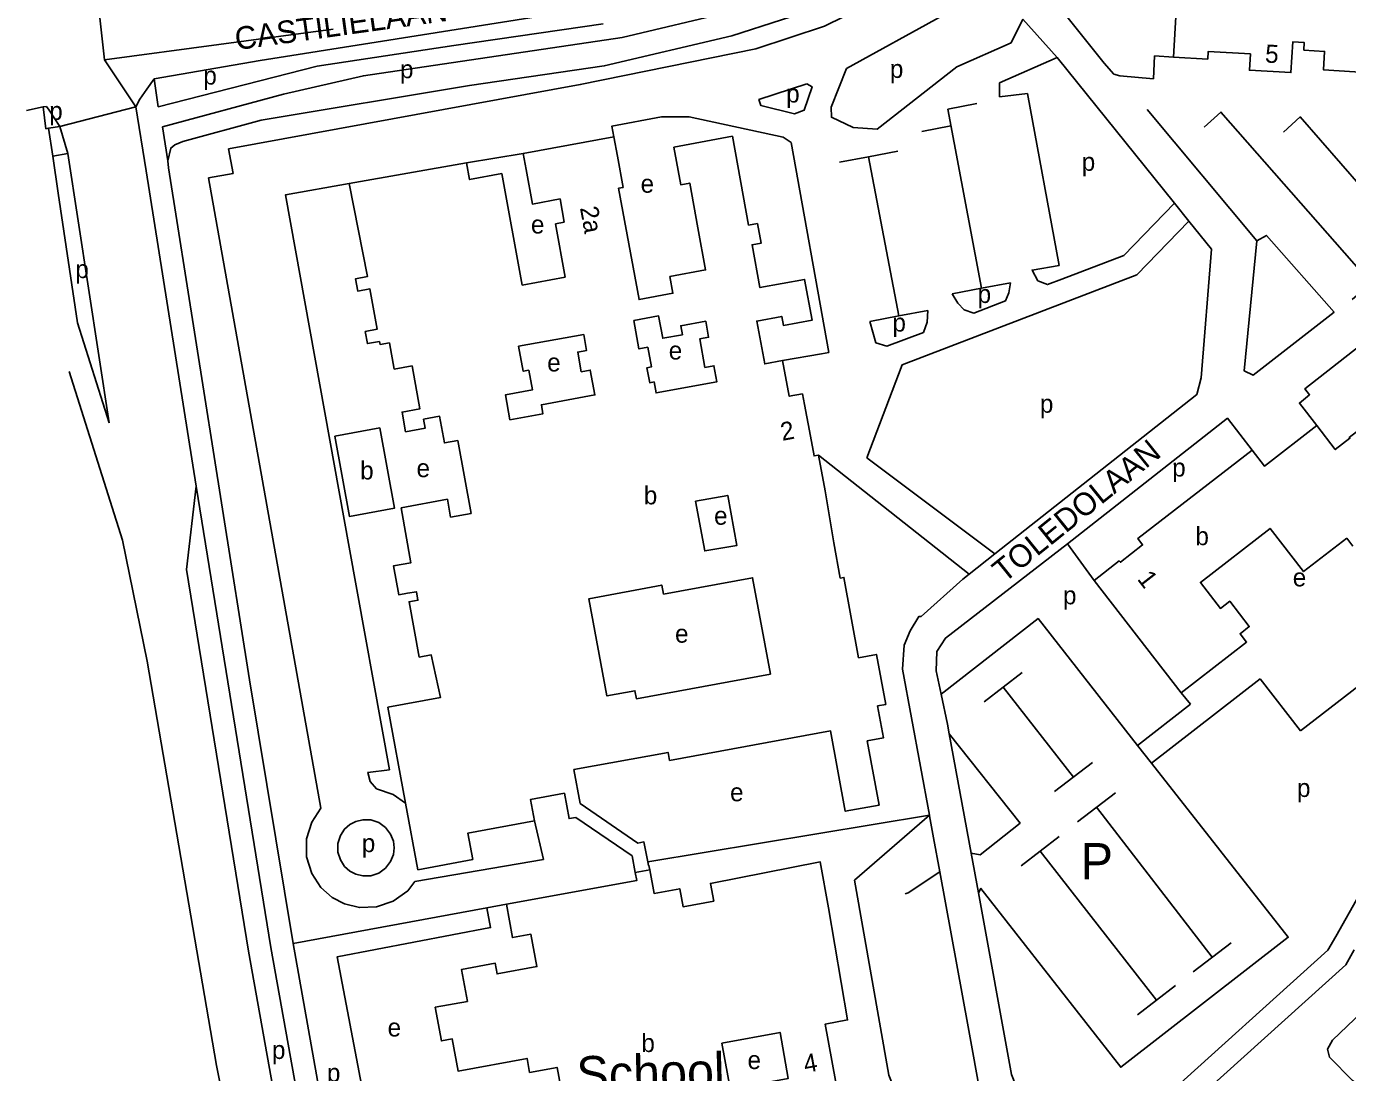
# Model space of a CAD drawing. Extents: x 159441 to 162086, y 388175 to 389787.
# Drawn here: x 159474.3 to 159765.8, y 388873.9 to 389104.6 of the extents above; entities that cross this region are included whole.
import ezdxf

# ---------------------------------------------------------------- set-up
doc = ezdxf.new("R2010")
doc.units = 0
for name, color, linetype in [('BLT_Basislijn', 7, 'Continuous'), ('BLT_Bebouwing', 7, 'Continuous'), ('BLT_Bebouwing_beschrifting', 7, 'Continuous'), ('BLT_Centroide', 7, 'Continuous'), ('BLT_Huisnummer', 7, 'Continuous'), ('BLT_Huisnummer_reeks', 7, 'Continuous'), ('BLT_Onderverdeling_panden', 7, 'Continuous'), ('BLT_Straatnaam', 7, 'Continuous'), ('BLT_Tekst_parkeren', 7, 'Continuous'), ('BLT_Vlakafsluiter', 7, 'Continuous')]:
    doc.layers.add(name, color=color, linetype=linetype)

msp = doc.modelspace()

# ---------------------------------------------------------------- linework, layer by layer
at = {"layer": 'BLT_Basislijn'}
for p, q in [((159568.59, 389100.37), (159601.53, 389105.17)), ((159541.95, 389104.04), (159491.51, 389097.27)), ((159538.39, 389095.84), (159568.59, 389100.37)), ((159727.33, 389097.85), (159723.18, 389098.14)), ((159479.24, 389086.16), (159478.7, 389086.98)), ((159677.54, 389086.37), (159683.95, 389087.58)), ((159498.37, 389086.88), (159500.66, 389072.78)), ((159677.54, 389086.37), (159684.95, 389046.87)), ((159479.15, 389082.14), (159481.62, 389082.54)), ((159671.82, 389081.47), (159678.23, 389082.68)), ((159480.07, 389075.99), (159483.43, 389076.56)), ((159583.85, 389076.61), (159571.34, 389074.53)), ((159653.67, 389074.66), (159660.08, 389075.87)), ((159660.08, 389075.87), (159666.49, 389077.08)), ((159511.68, 389003.22), (159500.66, 389072.78)), ((159678.54, 389045.66), (159684.95, 389046.87)), ((159684.95, 389046.87), (159691.36, 389048.08)), ((159660.31, 389039.55), (159666.71, 389040.76)), ((159666.71, 389040.76), (159673.12, 389041.97)), ((159682.24, 388983.81), (159649, 389010.05)), ((159509.6, 388984.81), (159511.68, 389003.22)), ((159682.24, 388983.81), (159687.91, 388988.28)), ((159709.85, 388982.41), (159703.94, 388990.47)), ((159685.55, 388955.64), (159693.92, 388962.08)), ((159689.73, 388958.86), (159705.3, 388939.04)), ((159722.51, 388942.1), (159746.45, 388960.72)), ((159719.42, 388946.03), (159731.07, 388955.09)), ((159719.42, 388946.03), (159722.51, 388942.1)), ((159701.11, 388935.82), (159709.49, 388942.26)), ((159706.15, 388929.16), (159714.53, 388935.59)), ((159611.35, 388920.37), (159673.49, 388930.61)), ((159710.34, 388932.38), (159735.88, 388899.29)), ((159674.38, 388925.61), (159675.81, 388918.17)), ((159693.72, 388919.47), (159702.1, 388925.91)), ((159697.91, 388922.69), (159723.58, 388889.81)), ((159533.12, 388902.32), (159575.83, 388910.17)), ((159575.83, 388910.17), (159580.15, 388911)), ((159731.69, 388896.07), (159740.07, 388902.51)), ((159719.39, 388886.59), (159727.77, 388893.03))]:
    msp.add_line(p, q, dxfattribs=at)
for points in [[(159525.86, 389097.11), (159551.4, 389101.15), (159604.37, 389109.5), (159624.03, 389113.78), (159632.93, 389116.43), (159648.23, 389121.53), (159666.92, 389129.4), (159672.01, 389132.06)], [(159504.28, 389082.44), (159530.95, 389089.7), (159548.62, 389093.73), (159605.67, 389102.2), (159629.93, 389107.91), (159644.32, 389112.21), (159664.93, 389120.53), (159679.73, 389127.81)], [(159688.15, 389129.13), (159695.07, 389117.86), (159712.06, 389096.47), (159714.2, 389094.06), (159715.53, 389093.71), (159722.91, 389093.05)], [(159505.46, 389074.96), (159506.1, 389077.76), (159506.99, 389078.46), (159508.78, 389079.21), (159526.06, 389083.91), (159572.01, 389091.55), (159601.73, 389095.89), (159629.93, 389102.55), (159651.83, 389109.56), (159662.94, 389114.27), (159681.99, 389123.7)], [(159694.13, 389106.22), (159691.51, 389100.96), (159679.57, 389095.67), (159661.96, 389081.94), (159656.66, 389082.33), (159651.86, 389084.58), (159651.82, 389086.78), (159655.2, 389095.33), (159676.31, 389106.98), (159673.6, 389111.89), (159671.73, 389115.27), (159650.36, 389104.68), (159635.16, 389099.67), (159596.44, 389091.79), (159518.87, 389077.6), (159519.87, 389072.19), (159514.45, 389071.2), (159539.21, 388932.17)], [(159694.13, 389106.22), (159701.68, 389097.78)], [(159525.86, 389097.11), (159502.44, 389093.04)], [(159502.44, 389093.04), (159503.35, 389086.91), (159538.39, 389095.84)], [(159688.96, 389089.06), (159688.96, 389092.14), (159701.68, 389097.78)], [(159727.57, 389065.59), (159701.68, 389097.78)], [(159723.18, 389098.14), (159722.91, 389093.05)], [(159502.44, 389093.04), (159500.79, 389090.79), (159499.29, 389088.55), (159498.37, 389086.88)], [(159477.92, 389086.87), (159478.7, 389086.98)], [(159688.96, 389089.06), (159695.12, 389089.8), (159702.13, 389051.9)], [(159479.15, 389082.14), (159478.56, 389082.05), (159477.92, 389086.87)], [(159479.24, 389086.16), (159480.35, 389084.48), (159481.62, 389082.54)], [(159641.1, 389030.9), (159649.66, 389032.43), (159651.28, 389032.72), (159642.98, 389078.99), (159641.21, 389080.22), (159620.48, 389084.7), (159614.39, 389084.68), (159603.4, 389082.61), (159603.87, 389080.25)], [(159721.55, 389086.27), (159745.75, 389057.32)], [(159734.1, 389082.4), (159737.82, 389085.73), (159770.97, 389047.99), (159766.8, 389044.4)], [(159751.6, 389081.32), (159755.32, 389084.64), (159777.7, 389058.95), (159773.53, 389055.36)], [(159479.15, 389082.14), (159480.07, 389075.99)], [(159481.62, 389082.54), (159481.62, 389082.54), (159483.43, 389076.56)], [(159505.46, 389074.96), (159504.28, 389082.44)], [(159480.07, 389075.99), (159481.29, 389067.86), (159485.55, 389039.22)], [(159483.43, 389076.56), (159492.52, 389017.15)], [(159660.08, 389075.87), (159666.71, 389040.76)], [(159533.12, 388902.32), (159523.51, 388960.52), (159505.62, 389073.43), (159505.46, 389074.96)], [(159551.47, 388936.47), (159550.11, 388938.04), (159549.57, 388940.05), (159554.36, 388940.66), (159545.47, 388989.77), (159531.41, 389067.43), (159545.5, 389069.98)], [(159702.7, 389048.83), (159716.42, 389054.09), (159727.57, 389065.59)], [(159730.73, 389061.66), (159727.57, 389065.59)], [(159659.72, 389009.44), (159667.5, 389029.99), (159719.24, 389049.81), (159730.73, 389061.66)], [(159687.91, 388988.28), (159732.51, 389023.44), (159733.43, 389027.1), (159735.71, 389055.46), (159730.73, 389061.66)], [(159745.75, 389057.32), (159742.96, 389028.61), (159744.91, 389027.69), (159762.76, 389041.6), (159747.86, 389058.53), (159745.75, 389057.32)], [(159702.7, 389048.83), (159699.58, 389047.66), (159697.44, 389048.5), (159696.15, 389050.87), (159702.13, 389051.9)], [(159678.54, 389045.66), (159679.77, 389043.58), (159681.18, 389042.11), (159683.29, 389041.4), (159690.3, 389044.08), (159691.03, 389045.86), (159691.36, 389048.08)], [(159660.31, 389039.55), (159661.7, 389034.83), (159664.13, 389034.06), (159672.15, 389037.13), (159672.99, 389039.38), (159673.12, 389041.97)], [(159492.52, 389017.15), (159485.55, 389039.22)], [(159516.2, 388875.39), (159500.92, 388964.62), (159495.43, 388991.33), (159483.69, 389028.51)], [(159703.94, 388990.47), (159739.24, 389018.18), (159744.67, 389011.18)], [(159659.72, 389009.44), (159687.91, 388988.28)], [(159528.2, 388901.44), (159511.68, 389003.22)], [(159755.35, 388949.25), (159825.31, 389003.26), (159836.51, 388988.75), (159851.63, 389000.41)], [(159676.07, 388957.31), (159674.97, 388962.49), (159675.16, 388966.73), (159677.02, 388969.69), (159703.94, 388990.47)], [(159523.27, 388900.61), (159509.6, 388984.81)], [(159673.49, 388930.61), (159667.57, 388962.83), (159667.91, 388968.16), (159669.27, 388971.26), (159671.15, 388974.45), (159671.7, 388974.48), (159680.85, 388982.72), (159682.24, 388983.81)], [(159719.42, 388946.03), (159697.45, 388973.99), (159676.07, 388957.31)], [(159746.45, 388960.72), (159755.35, 388949.25)], [(159677.87, 388948.58), (159677.48, 388950.68), (159676.07, 388957.31)], [(159729.05, 388957.64), (159731.07, 388955.09)], [(159677.87, 388948.58), (159693.5, 388928.89), (159684.7, 388921.91), (159682.68, 388922.26)], [(159682.68, 388922.26), (159677.87, 388948.58)], [(159684.29, 388913.5), (159684.85, 388914.49), (159715.72, 388875.03), (159752.67, 388903.72), (159722.51, 388942.1)], [(159557.93, 388933.25), (159555.19, 388935.22), (159551.47, 388936.47)], [(159539.21, 388932.17), (159537.21, 388929.12), (159536.07, 388925.42), (159536.07, 388921.45), (159537.21, 388917.74), (159539.21, 388914.7), (159541.68, 388912.51), (159544.41, 388911.08), (159547.74, 388910.27), (159551.47, 388910.4), (159555.19, 388911.65), (159558.4, 388913.96), (159559.96, 388916)], [(159555.39, 388923.43), (159555.22, 388924.92), (159554.61, 388926.47), (159553.51, 388927.9), (159552, 388928.99), (159550.25, 388929.58), (159548.49, 388929.64), (159546.92, 388929.26), (159545.63, 388928.58), (159544.47, 388927.55), (159543.53, 388926.12), (159542.99, 388924.37), (159542.99, 388922.5), (159543.53, 388920.75), (159544.47, 388919.32), (159545.63, 388918.29), (159546.92, 388917.61), (159548.49, 388917.23), (159550.25, 388917.29), (159552, 388917.88), (159553.51, 388918.97), (159554.61, 388920.4), (159555.22, 388921.95), (159555.39, 388923.43)], [(159555.39, 388923.43), (159555.22, 388924.92), (159554.61, 388926.47), (159553.51, 388927.9), (159552, 388928.99), (159550.25, 388929.58), (159548.49, 388929.64), (159546.92, 388929.26), (159545.63, 388928.58), (159544.47, 388927.55), (159543.53, 388926.12), (159542.99, 388924.37), (159542.99, 388922.5), (159543.53, 388920.75), (159544.47, 388919.32), (159545.63, 388918.29), (159546.92, 388917.61), (159548.49, 388917.23), (159550.25, 388917.29), (159552, 388917.88), (159553.51, 388918.97), (159554.61, 388920.4), (159555.22, 388921.95), (159555.39, 388923.43)], [(159669.85, 388852.06), (159667.68, 388856.68), (159666.83, 388867.61), (159664.51, 388873.26), (159656.97, 388916.29), (159673.49, 388930.61)], [(159674.38, 388925.61), (159673.52, 388930.49), (159673.49, 388930.61)], [(159586.36, 388929.42), (159588.33, 388920.87), (159559.96, 388916)], [(159684.29, 388913.5), (159682.68, 388922.26)], [(159668.13, 388913.31), (159668.83, 388913.47), (159675.81, 388918.17)], [(159684.94, 388867.88), (159684.89, 388868.11), (159682.07, 388883.93), (159675.81, 388918.17)], [(159697.68, 388847.59), (159701.34, 388848.91), (159702.83, 388850.15), (159704.42, 388852.44), (159704.97, 388854.99), (159704.74, 388857.86), (159703.72, 388860.26), (159700.85, 388863.36), (159695.89, 388866.29), (159695, 388867.2), (159692.7, 388870.67), (159691.62, 388873.45), (159684.29, 388913.5)], [(159763.13, 388903.88), (159768.42, 388913.16)], [(159575.83, 388910.17), (159576.65, 388905.85), (159542.83, 388899.41), (159548.51, 388869.63), (159552.99, 388870.48), (159556.99, 388865.42), (159564.21, 388860.39), (159568.48, 388840.16), (159561.91, 388830.94), (159558.08, 388833.68), (159552.62, 388826.02), (159571.12, 388812.83)], [(159724.37, 388867.45), (159761.4, 388900.83), (159763.13, 388903.88)], [(159523.27, 388900.61), (159529.85, 388863.64), (159538.83, 388818.68), (159546.39, 388781.17)], [(159528.2, 388901.44), (159534.77, 388864.57), (159543.73, 388819.66), (159551.28, 388782.22)], [(159533.12, 388902.32), (159539.68, 388865.5), (159548.63, 388820.64), (159555.19, 388788.11)], [(159729.45, 388865.3), (159765.35, 388897.66), (159767.19, 388900.9)], [(159534.45, 388783.62), (159516.2, 388875.39)]]:
    msp.add_lwpolyline(points, dxfattribs=at)
for points in [[(159646.45, 389091.98), (159635.87, 389088.49), (159636.31, 389087.14), (159643.75, 389085.34), (159645.89, 389086.13), (159647.63, 389091.25)], [(159770.53, 388888.73), (159762.42, 388881.03), (159761.31, 388879.03), (159761.77, 388877.29), (159766.86, 388872.12), (159774.36, 388866.64), (159781.77, 388864.18), (159786.92, 388864.38), (159790.25, 388866.1), (159792, 388868.39), (159793.07, 388872.08), (159791.46, 388875.51), (159788.44, 388879.12), (159786.19, 388881.02), (159782.61, 388883.16), (159775.29, 388888.55), (159773.94, 388889.54), (159772.14, 388889.56)]]:
    msp.add_lwpolyline(points, close=True, dxfattribs=at)
at = {"layer": 'BLT_Bebouwing'}
for p, q in [((159617.09, 389078.01), (159630.05, 389080.4)), ((159630.05, 389080.4), (159633.57, 389060.76)), ((159592.93, 389061.45), (159590.96, 389061.09)), ((159590.96, 389061.09), (159593.12, 389049.28)), ((159567.14, 389000.31), (159556.93, 388998.45)), ((159729.05, 388957.64), (159709.85, 388982.41)), ((159557.93, 388933.25), (159560.65, 388918.59)), ((159560.65, 388918.59), (159572.74, 388920.83))]:
    msp.add_line(p, q, dxfattribs=at)
for points in [[(159727.33, 389097.85), (159729.27, 389131.07)], [(159788.1, 389058.81), (159769.78, 389079.68), (159770.78, 389094.37), (159760.43, 389095.05), (159760.67, 389099.11), (159756.11, 389099.38), (159756.21, 389101.06), (159753.67, 389101.21), (159753.27, 389094.42), (159744.09, 389094.96), (159744.3, 389098.53), (159735.01, 389099.08), (159734.91, 389097.4), (159727.33, 389097.85)], [(159603.87, 389080.25), (159583.85, 389076.61)], [(159604.64, 389076.01), (159603.87, 389080.25)], [(159583.85, 389076.61), (159584.5, 389073.05), (159585.88, 389065.44), (159592, 389066.55), (159592.93, 389061.45)], [(159604.92, 389068.91), (159605.9, 389069.09), (159604.64, 389076.01)], [(159622.38, 389060.19), (159620.6, 389070.06), (159618.62, 389069.7), (159617.09, 389078.01)], [(159571.34, 389074.53), (159545.5, 389069.98)], [(159579.13, 389072.15), (159572.02, 389070.83), (159571.34, 389074.53)], [(159545.5, 389069.98), (159549.53, 389049.46), (159546.88, 389048.96), (159547.37, 389046.25), (159550.03, 389046.72), (159551.65, 389037.85), (159549.03, 389037.3), (159549.49, 389034.64), (159552.15, 389035.09), (159552.27, 389034.46), (159554.34, 389034.84)], [(159593.12, 389049.28), (159583.65, 389047.57), (159579.13, 389072.15)], [(159616.23, 389049.44), (159616.91, 389045.75), (159609.44, 389044.37), (159604.92, 389068.91)], [(159641.1, 389030.9), (159637.15, 389030.17), (159635.4, 389039.63), (159640.92, 389040.64), (159641.28, 389038.66), (159647.59, 389039.81), (159645.94, 389048.8), (159636.1, 389047), (159634.37, 389056.44), (159636.35, 389056.8), (159635.55, 389061.13), (159633.57, 389060.76)], [(159622.38, 389060.19), (159624.09, 389050.89), (159616.23, 389049.44)], [(159758.97, 389016.55), (159755.11, 389021.53), (159757.37, 389023.36), (159756.34, 389024.69), (159792.93, 389053.38), (159788.1, 389058.81)], [(159554.34, 389034.84), (159555.4, 389029.02), (159559.34, 389029.74), (159561.07, 389020.28), (159557.13, 389019.56), (159557.92, 389015.22), (159562.24, 389016.01), (159561.88, 389017.97), (159565.42, 389018.61), (159566.5, 389012.73), (159569.44, 389013.25), (159572.36, 388997.21)], [(159645.5, 389023.57), (159642.55, 389023.02), (159641.1, 389030.9)], [(159649, 389010.05), (159648.03, 389009.87), (159647.23, 389014.21), (159645.93, 389021.2), (159645.5, 389023.57)], [(159758.97, 389016.55), (159747.43, 389007.61), (159744.67, 389011.18)], [(159709.85, 388982.41), (159715.39, 388986.71), (159715.62, 388986.41), (159720.54, 388990.23), (159719.45, 388991.63), (159744.67, 389011.18)], [(159652.37, 388990.67), (159650.46, 389002.17), (159649, 389010.05)], [(159567.14, 389000.31), (159567.85, 388996.38), (159572.36, 388997.21)], [(159556.93, 388998.45), (159559.1, 388986.33), (159555.22, 388985.61), (159556.41, 388979.24), (159558.33, 388979.59), (159560.3, 388979.93), (159560.64, 388978.03), (159558.67, 388977.7), (159560.93, 388965.5), (159563.58, 388965.99), (159565.64, 388956.6), (159554.01, 388954.43), (159557.93, 388933.25)], [(159765.57, 388991.74), (159756.03, 388984.35), (159748.65, 388993.88), (159733.27, 388981.96), (159737.71, 388976.23), (159739.75, 388977.81), (159744.07, 388972.23), (159742.03, 388970.66), (159743.46, 388968.82), (159729.05, 388957.64)], [(159766.95, 388989.97), (159765.57, 388991.74)], [(159611.35, 388920.37), (159610.51, 388924.73), (159609.16, 388924.47), (159596.42, 388933.23), (159595.07, 388940.7), (159615.83, 388944.49), (159616.15, 388942.71), (159651.67, 388949.22), (159654.92, 388931.5), (159662.4, 388932.86), (159659.78, 388947.02), (159663.35, 388947.68), (159662.05, 388954.74), (159663.84, 388955.07), (159661.81, 388966.1), (159657.88, 388965.37), (159654.64, 388983.08), (159653.81, 388982.94), (159652.37, 388990.67)], [(159586.36, 388929.42), (159585.5, 388934.1), (159592.95, 388935.47), (159593.98, 388929.88), (159595.5, 388930.11), (159607.92, 388921.66), (159608.6, 388917.96)], [(159572.74, 388920.83), (159571.65, 388926.7), (159586.36, 388929.42)], [(159608.6, 388917.96), (159608.92, 388916.22), (159580.15, 388911)], [(159611.81, 388918.56), (159611.62, 388919.57), (159611.5, 388919.55), (159611.35, 388920.37)], [(159625.9, 388911.66), (159619.13, 388910.42), (159618.42, 388914.41), (159612.75, 388913.38), (159611.81, 388918.56)], [(159651.23, 388910.21), (159649.39, 388920.32), (159625.18, 388915.57), (159625.9, 388911.66)], [(159580.15, 388911), (159581.5, 388903.62), (159585.58, 388904.37), (159586.89, 388897.22), (159578.11, 388895.62), (159577.68, 388897.98), (159570.26, 388896.62), (159571.56, 388889.55), (159564.47, 388888.25), (159565.83, 388880.84), (159568.2, 388881.28), (159569.5, 388874.2), (159584.72, 388877), (159585.29, 388873.89), (159591.35, 388875), (159592.6, 388868.24)], [(159655.34, 388863.48), (159654.41, 388863.31), (159650.5, 388884.57), (159655.42, 388885.46), (159651.23, 388910.21)]]:
    msp.add_lwpolyline(points, dxfattribs=at)
for points in [[(159608.24, 389039.73), (159613.75, 389040.74), (159614.65, 389035.82), (159618.98, 389036.61), (159618.62, 389038.58), (159624.13, 389039.59), (159624.78, 389036.05), (159622.81, 389035.69), (159623.96, 389029.39), (159625.93, 389029.75), (159626.58, 389026.21), (159613.2, 389023.76), (159612.75, 389026.2), (159611.77, 389026.02), (159611.16, 389029.33), (159612.15, 389029.51), (159611.36, 389033.83), (159609.39, 389033.47)], [(159597.21, 389036.69), (159582.85, 389034.06), (159583.86, 389028.55), (159585.08, 389028.77), (159585.88, 389024.44), (159579.93, 389023.35), (159580.94, 389017.84), (159588.23, 389019.18), (159587.87, 389021.15), (159599.67, 389023.32), (159598.66, 389028.82), (159596.69, 389028.46), (159595.89, 389032.79), (159597.86, 389033.15)], [(159542.29, 389014.24), (159545.53, 388996.53), (159555.46, 388998.35), (159552.22, 389016.06)], [(159621.86, 388999.88), (159629.01, 389001.18), (159631.02, 388990.13), (159623.93, 388988.91)], [(159614.79, 388979.41), (159614.42, 388981.4), (159598.37, 388978.37), (159598.37, 388978.37), (159602.33, 388956.93), (159608.52, 388958.08), (159608.85, 388956.31), (159638.42, 388961.77), (159634.49, 388983.01)], [(159627.72, 388880.37), (159640.54, 388882.73), (159642.32, 388872.53), (159635.15, 388871.23), (159636.43, 388864.16), (159630.84, 388863.15)]]:
    msp.add_lwpolyline(points, close=True, dxfattribs=at)
at = {"layer": 'BLT_Onderverdeling_panden'}
msp.add_line((159608.6, 388917.96), (159611.81, 388918.56), dxfattribs=at)
msp.add_lwpolyline([(159777.96, 389022.73), (159774.75, 389020.23), (159774.56, 389020.48), (159766.14, 389013.95), (159766.27, 389013.79), (159763.05, 389011.29), (159758.97, 389016.55)], dxfattribs=at)
at = {"layer": 'BLT_Vlakafsluiter'}
for p, q in [((159491.51, 389097.27), (159489.56, 389114.25)), ((159491.51, 389097.27), (159498.37, 389086.88)), ((159474.26, 389086.05), (159477.92, 389086.87)), ((159481.62, 389082.54), (159498.37, 389086.88))]:
    msp.add_line(p, q, dxfattribs=at)

# ---------------------------------------------------------------- texts
at = {"layer": 'BLT_Bebouwing_beschrifting'}
msp.add_text('School', height=8, rotation=1.5067, dxfattribs=at).set_placement((159595.72, 388869.42))
at = {"layer": 'BLT_Centroide'}
for s, p in [('p', (159556.68, 389093.18)), ('p', (159664.77, 389093.25)), ('p', (159513.29, 389091.78)), ('p', (159641.89, 389087.82)), ('p', (159479.29, 389083.99)), ('p', (159707.1, 389072.76)), ('e', (159609.77, 389067.93)), ('e', (159585.58, 389058.94)), ('p', (159485.05, 389049.09)), ('p', (159684.13, 389043.61)), ('p', (159665.33, 389037.3)), ('e', (159589.16, 389028.51)), ('e', (159615.98, 389031.14)), ('p', (159697.87, 389019.4)), ('b', (159547.9, 389004.68)), ('e', (159560.33, 389005.19)), ('p', (159727.06, 389005.33)), ('b', (159610.48, 388999.19)), ('e', (159625.98, 388994.7)), ('b', (159732.18, 388990.19)), ('e', (159753.66, 388981.1)), ('p', (159702.96, 388977.14)), ('e', (159617.37, 388968.68)), ('e', (159629.51, 388933.7)), ('p', (159754.59, 388934.65)), ('p', (159548.26, 388922.48)), ('e', (159553.95, 388881.82)), ('p', (159528.43, 388876.86)), ('b', (159609.94, 388878.39)), ('e', (159633.36, 388874.64)), ('p', (159540.56, 388871.82))]:
    msp.add_text(s, height=4, dxfattribs=at).set_placement(p)
at = {"layer": 'BLT_Huisnummer'}
for s, rotation, p in [('5', 356.6171, (159747.47, 389096.66)), ('1', 307.7895, (159719.2, 388982.69)), ('4', 10.5067, (159646.11, 388873.74))]:
    msp.add_text(s, height=4, rotation=rotation, dxfattribs=at).set_placement(p)
at = {"layer": 'BLT_Huisnummer_reeks'}
for s, rotation, p in [('2a', 280.3382, (159596.37, 389064.61)), ('2', 10.3975, (159641.02, 389013.19))]:
    msp.add_text(s, height=4, rotation=rotation, dxfattribs=at).set_placement(p)
at = {"layer": 'BLT_Straatnaam'}
for s, rotation, p in [('CASTILIELAAN', 7.9013, (159520.61, 389099.37)), ('TOLEDOLAAN', 38.9054, (159689.97, 388981.74))]:
    msp.add_text(s, height=5, rotation=rotation, dxfattribs=at).set_placement(p)
at = {"layer": 'BLT_Tekst_parkeren'}
msp.add_text('P', height=8, dxfattribs=at).set_placement((159706.86, 388916.48))

doc.saveas('drawing.dxf')
